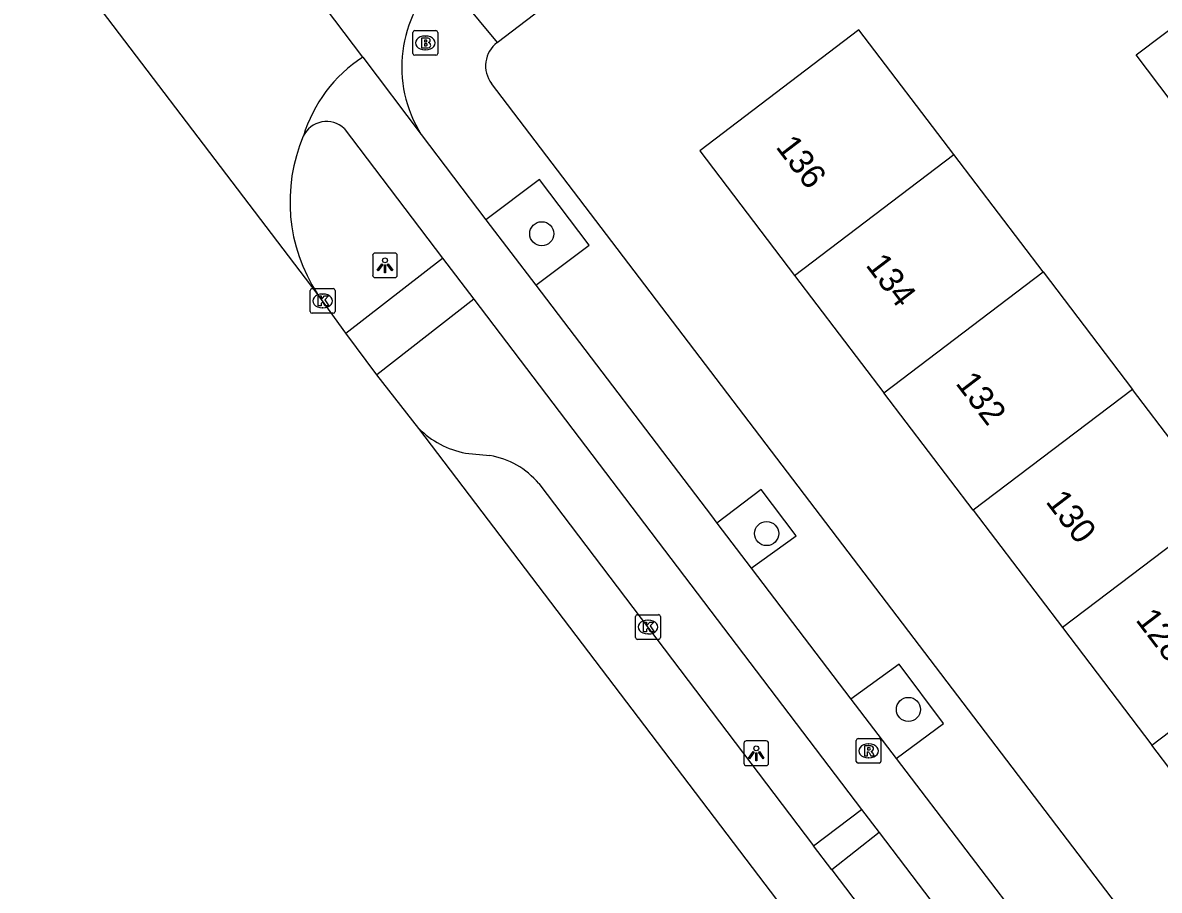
# Model space of a CAD drawing. Extents: x 160037 to 160839, y 385326 to 386441.
# Drawn here: x 160212.48 to 160258.53, y 385819.23 to 385854.38 of the extents above; entities that cross this region are included whole.
import ezdxf

# ---------------------------------------------------------------- set-up
doc = ezdxf.new("R2010")
doc.units = 0
for name, color, linetype in [('IMGEO_Boom', 7, 'Continuous'), ('IMGEO_Brandkraan', 7, 'Continuous'), ('IMGEO_Fietspad_gesloten', 7, 'Continuous'), ('IMGEO_Kolk', 7, 'Continuous'), ('IMGEO_Lichtpunt', 7, 'Continuous'), ('IMGEO_Pand', 7, 'Continuous'), ('IMGEO_Pand_nummerreeks', 7, 'Continuous'), ('IMGEO_Parkeervlak_open', 7, 'Continuous'), ('IMGEO_Rijbaan_lokaal_gesloten', 7, 'Continuous'), ('IMGEO_Rijbaan_lokaal_open', 7, 'Continuous'), ('IMGEO_Rioolput', 7, 'Continuous'), ('IMGEO_Voetpad_open', 7, 'Continuous')]:
    doc.layers.add(name, color=color, linetype=linetype)

msp = doc.modelspace()

# ---------------------------------------------------------------- linework, layer by layer
at = {"layer": 'IMGEO_Boom'}
for centre in [(160233.51, 385845.83), (160242.62, 385833.683), (160248.364, 385826.556)]:
    msp.add_circle(centre, 0.489, dxfattribs=at)
at = {"layer": 'IMGEO_Brandkraan'}
for p, q in [((160228.293, 385853.135), (160228.293, 385853.987)), ((160228.368, 385854.061), (160229.22, 385854.061)), ((160229.294, 385853.987), (160229.294, 385853.135)), ((160228.781, 385853.841), (160228.806, 385853.841)), ((160229.22, 385853.061), (160228.368, 385853.061)), ((160228.804, 385853.281), (160228.779, 385853.281))]:
    msp.add_line(p, q, dxfattribs=at)
for points in [[(160228.293, 385853.135), (160228.293, 385853.987)], [(160228.368, 385854.061), (160229.22, 385854.061)], [(160229.294, 385853.987), (160229.294, 385853.135)], [(160228.641, 385853.761), (160228.641, 385853.361), (160228.854, 385853.361)], [(160228.872, 385853.761), (160228.641, 385853.761)], [(160228.82, 385853.68), (160228.766, 385853.68), (160228.766, 385853.604)], [(160228.766, 385853.604), (160228.819, 385853.604)], [(160228.828, 385853.528), (160228.766, 385853.528), (160228.766, 385853.447)], [(160229.22, 385853.061), (160228.368, 385853.061)], [(160228.766, 385853.447), (160228.828, 385853.447)]]:
    msp.add_lwpolyline(points, dxfattribs=at)
for centre, radius, start, end in [((160228.37, 385853.985), 0.0765, 91.552, 178.448), ((160228.37, 385853.985), 0.0765, 91.552, 178.448), ((160229.218, 385853.985), 0.0765, 1.552, 88.448), ((160229.218, 385853.985), 0.0765, 1.552, 88.448), ((160228.821, 385853.642), 0.0379, 267.8285, 90.9355), ((160228.829, 385853.487), 0.0404, 269.8759, 90.5077), ((160228.876, 385853.616), 0.145, 59.4692, 91.5367), ((160228.901, 385853.663), 0.0922, 285.5137, 58.1501), ((160228.906, 385853.471), 0.105, 301.3115, 78.989), ((160228.37, 385853.137), 0.0765, 181.552, 268.448), ((160228.37, 385853.137), 0.0765, 181.552, 268.448), ((160228.86, 385853.612), 0.251, 268.6676, 293.5347), ((160229.218, 385853.137), 0.0765, 271.552, 358.448), ((160229.218, 385853.137), 0.0765, 271.552, 358.448)]:
    msp.add_arc(centre, radius, start, end, dxfattribs=at)
for centre, major_axis, ratio, start_param, end_param in [((160228.78, 385853.561), (-0.387, 0.002), 0.722429, 4.712389, 7.853982), ((160228.805, 385853.561), (-0.39, 0.002), 0.717154, 1.570796, 4.712389)]:
    msp.add_ellipse(centre, major_axis=major_axis, ratio=ratio, start_param=start_param, end_param=end_param, dxfattribs=at)
at = {"layer": 'IMGEO_Fietspad_gesloten'}
for points in [[(160225.501, 385850.09), (160229.487, 385844.842)], [(160228.63, 385849.846), (160231.245, 385846.393)], [(160231.245, 385846.393), (160233.264, 385843.741)], [(160229.487, 385844.842), (160230.756, 385843.173)], [(160233.264, 385843.741), (160240.383, 385834.395), (160240.606, 385834.102)], [(160230.756, 385843.173), (160246.466, 385822.505)], [(160240.606, 385834.102), (160241.998, 385832.275)], [(160241.998, 385832.275), (160246.034, 385826.977)], [(160246.034, 385826.977), (160247.864, 385824.573)], [(160247.864, 385824.573), (160253.509, 385817.161), (160253.742, 385816.855)], [(160246.466, 385822.505), (160247.179, 385821.566)], [(160247.179, 385821.566), (160265.333, 385797.683)]]:
    msp.add_lwpolyline(points, dxfattribs=at)
msp.add_arc((160224.786, 385849.347), 1.031, 46.0663, 155.1353, dxfattribs=at)
at = {"layer": 'IMGEO_Kolk'}
for p, q in [((160224.133, 385842.682), (160224.133, 385843.534)), ((160224.208, 385843.608), (160225.06, 385843.608)), ((160224.621, 385843.388), (160224.646, 385843.388)), ((160225.134, 385843.534), (160225.134, 385842.682)), ((160225.06, 385842.608), (160224.208, 385842.608)), ((160224.644, 385842.828), (160224.619, 385842.828)), ((160237.313, 385829.47), (160237.313, 385830.322)), ((160237.388, 385830.396), (160238.24, 385830.396)), ((160237.801, 385830.176), (160237.826, 385830.176)), ((160238.314, 385830.322), (160238.314, 385829.47)), ((160237.824, 385829.616), (160237.799, 385829.616)), ((160238.24, 385829.396), (160237.388, 385829.396))]:
    msp.add_line(p, q, dxfattribs=at)
for points in [[(160224.133, 385842.682), (160224.133, 385843.534)], [(160224.208, 385843.608), (160225.06, 385843.608)], [(160225.134, 385843.534), (160225.134, 385842.682)], [(160224.454, 385843.308), (160224.577, 385843.308), (160224.577, 385843.157), (160224.707, 385843.308), (160224.871, 385843.308), (160224.725, 385843.157), (160224.878, 385842.908), (160224.726, 385842.908), (160224.641, 385843.072), (160224.577, 385843.005), (160224.577, 385842.908), (160224.454, 385842.908), (160224.454, 385843.308)], [(160225.06, 385842.608), (160224.208, 385842.608)], [(160237.313, 385829.47), (160237.313, 385830.322)], [(160237.388, 385830.396), (160238.24, 385830.396)], [(160237.634, 385830.096), (160237.757, 385830.096), (160237.757, 385829.945), (160237.887, 385830.096), (160238.051, 385830.096), (160237.905, 385829.945), (160238.058, 385829.696), (160237.906, 385829.696), (160237.821, 385829.86), (160237.757, 385829.793), (160237.757, 385829.696), (160237.634, 385829.696), (160237.634, 385830.096)], [(160238.314, 385830.322), (160238.314, 385829.47)], [(160238.24, 385829.396), (160237.388, 385829.396)]]:
    msp.add_lwpolyline(points, dxfattribs=at)
for centre, start, end in [((160224.21, 385843.532), 91.552, 178.448), ((160224.21, 385843.532), 91.552, 178.448), ((160225.058, 385843.532), 1.552, 88.448), ((160225.058, 385843.532), 1.552, 88.448), ((160224.21, 385842.684), 181.552, 268.448), ((160224.21, 385842.684), 181.552, 268.448), ((160225.058, 385842.684), 271.552, 358.448), ((160225.058, 385842.684), 271.552, 358.448), ((160237.39, 385830.32), 91.552, 178.448), ((160237.39, 385830.32), 91.552, 178.448), ((160238.238, 385830.32), 1.552, 88.448), ((160238.238, 385830.32), 1.552, 88.448), ((160237.39, 385829.472), 181.552, 268.448), ((160237.39, 385829.472), 181.552, 268.448), ((160238.238, 385829.472), 271.552, 358.448), ((160238.238, 385829.472), 271.552, 358.448)]:
    msp.add_arc(centre, 0.0765, start, end, dxfattribs=at)
for centre, major_axis, ratio, start_param, end_param in [((160224.62, 385843.108), (-0.387, 0.002), 0.722429, 4.712389, 7.853982), ((160224.645, 385843.108), (-0.39, 0.002), 0.717154, 1.570796, 4.712389), ((160237.8, 385829.896), (-0.387, 0.002), 0.722429, 4.712389, 7.853982), ((160237.825, 385829.896), (-0.39, 0.002), 0.717154, 1.570796, 4.712389)]:
    msp.add_ellipse(centre, major_axis=major_axis, ratio=ratio, start_param=start_param, end_param=end_param, dxfattribs=at)
at = {"layer": 'IMGEO_Lichtpunt'}
for p, q in [((160226.66, 385844.954), (160226.66, 385844.147)), ((160226.66, 385844.954), (160226.66, 385844.147)), ((160227.562, 385845.049), (160226.754, 385845.049)), ((160227.562, 385845.049), (160226.754, 385845.049)), ((160227.656, 385844.147), (160227.656, 385844.954)), ((160227.656, 385844.147), (160227.656, 385844.954)), ((160226.754, 385844.053), (160227.562, 385844.053)), ((160226.754, 385844.053), (160227.562, 385844.053)), ((160241.701, 385825.184), (160241.701, 385824.377)), ((160241.701, 385825.184), (160241.701, 385824.377)), ((160242.603, 385825.279), (160241.795, 385825.279)), ((160242.603, 385825.279), (160241.795, 385825.279)), ((160242.697, 385824.377), (160242.697, 385825.184)), ((160242.697, 385824.377), (160242.697, 385825.184)), ((160241.795, 385824.283), (160242.603, 385824.283)), ((160241.795, 385824.283), (160242.603, 385824.283))]:
    msp.add_line(p, q, dxfattribs=at)
for points in [[(160227.034, 385844.618), (160227.073, 385844.59), (160226.885, 385844.328), (160226.847, 385844.355), (160227.034, 385844.618)], [(160227.136, 385844.57), (160227.183, 385844.57), (160227.183, 385844.248), (160227.136, 385844.248), (160227.136, 385844.57)], [(160227.246, 385844.59), (160227.284, 385844.617), (160227.471, 385844.355), (160227.432, 385844.327), (160227.246, 385844.59)], [(160242.075, 385824.848), (160242.114, 385824.82), (160241.926, 385824.558), (160241.888, 385824.585), (160242.075, 385824.848)], [(160242.177, 385824.8), (160242.224, 385824.8), (160242.224, 385824.478), (160242.177, 385824.478), (160242.177, 385824.8)], [(160242.287, 385824.82), (160242.325, 385824.847), (160242.512, 385824.585), (160242.473, 385824.557), (160242.287, 385824.82)]]:
    msp.add_lwpolyline(points, dxfattribs=at)
for centre in [(160227.159, 385844.752), (160242.2, 385824.982)]:
    msp.add_circle(centre, 0.0994, dxfattribs=at)
for centre, start, end in [((160226.754, 385844.954), 90, 180), ((160226.754, 385844.954), 90, 180), ((160227.562, 385844.954), 0, 90), ((160227.562, 385844.954), 0, 90), ((160226.754, 385844.147), 180, 270), ((160226.754, 385844.147), 180, 270), ((160227.562, 385844.147), 270, 0), ((160227.562, 385844.147), 270, 360), ((160241.795, 385825.184), 90, 180), ((160241.795, 385825.184), 90, 180), ((160242.603, 385825.184), 0, 90), ((160242.603, 385825.184), 0, 90), ((160241.795, 385824.377), 180, 270), ((160241.795, 385824.377), 180, 270), ((160242.603, 385824.377), 270, 0), ((160242.603, 385824.377), 270, 360)]:
    msp.add_arc(centre, 0.0946, start, end, dxfattribs=at)
at = {"layer": 'IMGEO_Pand'}
for points in [[(160260.431, 385849.321), (160257.588, 385853.075), (160259.832, 385854.773)], [(160250.206, 385849.038), (160246.36, 385854.094), (160239.913, 385849.19), (160243.752, 385844.143)], [(160243.752, 385844.143), (160250.206, 385849.038)], [(160253.824, 385844.281), (160250.206, 385849.038)], [(160247.371, 385839.385), (160253.824, 385844.281)], [(160253.824, 385844.281), (160257.443, 385839.524)], [(160243.752, 385844.143), (160247.371, 385839.385)], [(160250.989, 385834.629), (160247.371, 385839.385)], [(160257.443, 385839.524), (160250.989, 385834.629)], [(160260.981, 385834.873), (160257.443, 385839.524)], [(160250.989, 385834.629), (160254.608, 385829.871)], [(160260.981, 385834.873), (160261.061, 385834.768), (160254.608, 385829.871)], [(160258.227, 385825.114), (160264.68, 385830.01)], [(160254.608, 385829.871), (160258.227, 385825.114)], [(160261.846, 385820.356), (160258.227, 385825.114)]]:
    msp.add_lwpolyline(points, dxfattribs=at)
at = {"layer": 'IMGEO_Parkeervlak_open'}
for points in [[(160230.415, 385836.941), (160231.406, 385836.84)], [(160233.389, 385835.707), (160244.52, 385821.036)], [(160245.256, 385820.064), (160263.382, 385796.182)]]:
    msp.add_lwpolyline(points, dxfattribs=at)
for centre, radius, start, end in [((160231.129, 385840.566), 3.695, 225.2086, 258.8576), ((160230.928, 385833.702), 3.174, 39.1719, 81.3446)]:
    msp.add_arc(centre, radius, start, end, dxfattribs=at)
at = {"layer": 'IMGEO_Rijbaan_lokaal_gesloten'}
for points in [[(160224.418, 385843.405), (160212.483, 385859.092)], [(160226.256, 385852.983), (160222.149, 385858.445)], [(160225.579, 385841.807), (160224.418, 385843.405)], [(160226.826, 385840.11), (160225.579, 385841.807)], [(160228.526, 385837.944), (160226.826, 385840.11)], [(160279.223, 385771.231), (160228.526, 385837.944)]]:
    msp.add_lwpolyline(points, dxfattribs=at)
for centre, radius, start, end in [((160229.409, 385848.109), 5.804, 122.8962, 163.261), ((160230.103, 385847.125), 6.794, 156.9847, 213.1968)]:
    msp.add_arc(centre, radius, start, end, dxfattribs=at)
at = {"layer": 'IMGEO_Rijbaan_lokaal_open'}
msp.add_lwpolyline([(160226.256, 385852.983), (160228.63, 385849.846)], dxfattribs=at)
msp.add_arc((160232.958, 385852.584), 5.121, 133.3271, 212.316, dxfattribs=at)
at = {"layer": 'IMGEO_Rioolput'}
for p, q in [((160246.251, 385824.452), (160246.251, 385825.304)), ((160246.326, 385825.378), (160247.178, 385825.378)), ((160246.739, 385825.158), (160246.764, 385825.158)), ((160247.252, 385825.304), (160247.252, 385824.452)), ((160246.762, 385824.598), (160246.737, 385824.598)), ((160247.178, 385824.378), (160246.326, 385824.378))]:
    msp.add_line(p, q, dxfattribs=at)
for points in [[(160246.251, 385824.452), (160246.251, 385825.304)], [(160246.326, 385825.378), (160247.178, 385825.378)], [(160246.84, 385825.076), (160246.588, 385825.078), (160246.588, 385824.678)], [(160246.766, 385824.997), (160246.712, 385824.997), (160246.712, 385824.916)], [(160247.252, 385825.304), (160247.252, 385824.452)], [(160246.588, 385824.678), (160246.712, 385824.678), (160246.712, 385824.84), (160246.723, 385824.84)], [(160246.712, 385824.916), (160246.764, 385824.916)], [(160246.77, 385824.811), (160246.841, 385824.678), (160246.981, 385824.678), (160246.916, 385824.804)], [(160247.178, 385824.378), (160246.326, 385824.378)]]:
    msp.add_lwpolyline(points, dxfattribs=at)
for centre, radius, start, end in [((160246.328, 385825.302), 0.0765, 91.552, 178.448), ((160246.328, 385825.302), 0.0765, 91.552, 178.448), ((160246.772, 385824.901), 0.0964, 77.0061, 93.1865), ((160246.786, 385824.958), 0.0378, 276.6634, 79.6772), ((160246.839, 385824.966), 0.109, 350.3612, 89.416), ((160246.837, 385824.966), 0.112, 277.5842, 350.9817), ((160247.176, 385825.302), 0.0765, 1.552, 88.448), ((160247.176, 385825.302), 0.0765, 1.552, 88.448), ((160246.722, 385824.787), 0.0533, 26.0293, 88.6989), ((160246.748, 385825.105), 0.19, 274.7715, 282.9687), ((160246.821, 385824.751), 0.108, 29.5134, 73.7905), ((160246.328, 385824.454), 0.0765, 181.552, 268.448), ((160246.328, 385824.454), 0.0765, 181.552, 268.448), ((160247.176, 385824.454), 0.0765, 271.552, 358.448), ((160247.176, 385824.454), 0.0765, 271.552, 358.448)]:
    msp.add_arc(centre, radius, start, end, dxfattribs=at)
for centre, major_axis, ratio, start_param, end_param in [((160246.738, 385824.878), (-0.387, 0.002), 0.722429, 4.712389, 7.853982), ((160246.763, 385824.878), (-0.39, 0.002), 0.717154, 1.570796, 4.712389)]:
    msp.add_ellipse(centre, major_axis=major_axis, ratio=ratio, start_param=start_param, end_param=end_param, dxfattribs=at)
at = {"layer": 'IMGEO_Voetpad_open'}
for points in [[(160231.698, 385853.575), (160250.09, 385867.593)], [(160229.444, 385856.309), (160231.698, 385853.575)], [(160294.583, 385769.052), (160231.475, 385851.922)], [(160233.264, 385843.741), (160235.425, 385845.37), (160233.413, 385848.023), (160231.245, 385846.393)], [(160225.579, 385841.807), (160229.487, 385844.842)], [(160230.756, 385843.173), (160226.826, 385840.11)], [(160241.998, 385832.275), (160243.811, 385833.588), (160242.401, 385835.469), (160240.606, 385834.102)], [(160247.864, 385824.573), (160249.79, 385825.991), (160247.987, 385828.396), (160246.034, 385826.977)], [(160244.52, 385821.036), (160246.466, 385822.505)], [(160247.179, 385821.566), (160245.256, 385820.064)], [(160245.256, 385820.064), (160244.52, 385821.036)]]:
    msp.add_lwpolyline(points, dxfattribs=at)
msp.add_arc((160232.412, 385852.637), 1.179, 127.2942, 217.3395, dxfattribs=at)

# ---------------------------------------------------------------- texts
at = {"layer": 'IMGEO_Pand_nummerreeks'}
for s, rotation, p in [('136', 307.2591, (160242.961, 385849.344)), ('134', 307.2591, (160246.605, 385844.554)), ('132', 307.2591, (160250.248, 385839.765)), ('130', 307.2592, (160253.897, 385834.969)), ('128', 307.2592, (160257.541, 385830.179))]:
    msp.add_text(s, height=1, rotation=rotation, dxfattribs=at).set_placement(p)

doc.saveas('drawing.dxf')
